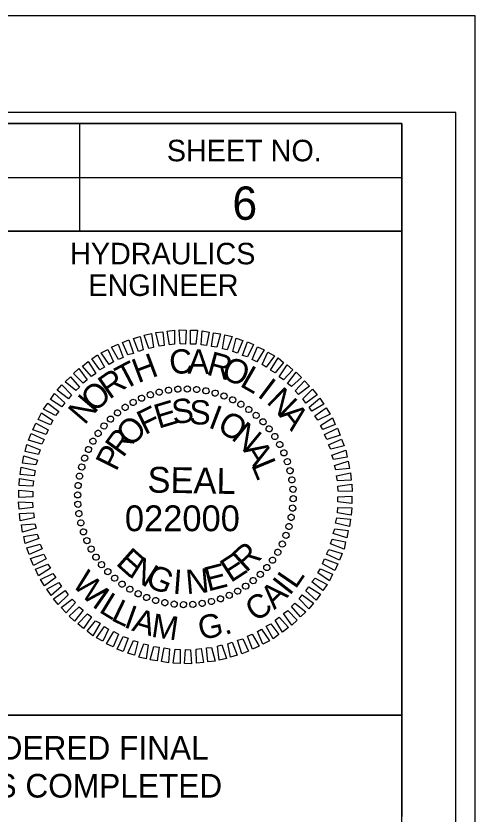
# Model space of a CAD drawing. Extents: x 1019474 to 1021158, y 503201 to 504732.
# Drawn here: x 1021051.4 to 1021158.2, y 504115.2 to 504300.7 of the extents above; entities that cross this region are included whole.
import ezdxf

# ---------------------------------------------------------------- set-up
doc = ezdxf.new("R2010")
doc.units = 0
for name, color, linetype in [('Sheet Cutting Line CELL', 7, 'Continuous'), ('Sheet Data Field CELL', 7, 'Continuous'), ('Sheet Plot Border Inside CELL', 7, 'Continuous'), ('Sheet Plot Border Outside CELL', 7, 'Continuous'), ('Sheet Professional Seal CELL', 7, 'Continuous'), ('Sheet Profile CELL', 7, 'Continuous'), ('Sheet Sticker Exception Certification CELL', 7, 'Continuous')]:
    doc.layers.add(name, color=color, linetype=linetype)

msp = doc.modelspace()

# ---------------------------------------------------------------- linework, layer by layer
at = {"layer": 'Sheet Cutting Line CELL'}
msp.add_line((1021158.22, 504300.7), (1019474.22, 504300.7), dxfattribs=at)
at = {"layer": 'Sheet Plot Border Inside CELL'}
msp.add_lwpolyline([(1019487.22, 503223.15), (1021153.72, 503223.15), (1021153.72, 504278.25), (1019487.22, 504278.25)], close=True, dxfattribs=at)
at = {"layer": 'Sheet Plot Border Outside CELL'}
msp.add_lwpolyline([(1019474.22, 503200.7), (1021158.22, 503200.7), (1021158.22, 504300.7), (1019474.22, 504300.7)], close=True, dxfattribs=at)
at = {"layer": 'Sheet Professional Seal CELL'}
for p, q in [((1021082.64, 504212.67), (1021082.64, 504212.67)), ((1021084.74, 504213.27), (1021084.74, 504213.27)), ((1021086.94, 504213.67), (1021086.94, 504213.67)), ((1021089.09, 504213.97), (1021089.09, 504213.97)), ((1021091.29, 504214.02), (1021091.29, 504214.02)), ((1021093.49, 504213.87), (1021093.49, 504213.87)), ((1021095.64, 504213.52), (1021095.64, 504213.52)), ((1021097.74, 504213.07), (1021097.74, 504213.07)), ((1021078.69, 504210.87), (1021078.69, 504210.87)), ((1021080.64, 504211.87), (1021080.64, 504211.87)), ((1021099.84, 504212.37), (1021099.84, 504212.37)), ((1021101.84, 504211.47), (1021101.84, 504211.47)), ((1021076.79, 504209.72), (1021076.79, 504209.72)), ((1021103.79, 504210.47), (1021103.79, 504210.47)), ((1021105.59, 504209.22), (1021105.59, 504209.22)), ((1021073.39, 504206.97), (1021073.39, 504206.97)), ((1021075.04, 504208.47), (1021075.04, 504208.47)), ((1021107.34, 504207.87), (1021107.34, 504207.87)), ((1021071.89, 504205.42), (1021071.89, 504205.42)), ((1021108.89, 504206.37), (1021108.89, 504206.37)), ((1021070.54, 504203.67), (1021070.54, 504203.67)), ((1021110.39, 504204.72), (1021110.39, 504204.72)), ((1021069.29, 504201.87), (1021069.29, 504201.87)), ((1021111.64, 504202.97), (1021111.64, 504202.97)), ((1021068.29, 504199.92), (1021068.29, 504199.92)), ((1021112.79, 504201.07), (1021112.79, 504201.07)), ((1021067.39, 504197.92), (1021067.39, 504197.92)), ((1021113.79, 504199.12), (1021113.79, 504199.12)), ((1021066.69, 504195.82), (1021066.69, 504195.82)), ((1021114.59, 504197.12), (1021114.59, 504197.12)), ((1021115.19, 504195.02), (1021115.19, 504195.02)), ((1021066.24, 504193.72), (1021066.24, 504193.72)), ((1021115.59, 504192.82), (1021115.59, 504192.82)), ((1021065.89, 504191.57), (1021065.89, 504191.57)), ((1021115.89, 504190.67), (1021115.89, 504190.67)), ((1021065.74, 504189.37), (1021065.74, 504189.37)), ((1021090.84, 504188.92), (1021090.84, 504188.92)), ((1021115.94, 504188.47), (1021115.94, 504188.47)), ((1021065.79, 504187.17), (1021065.79, 504187.17)), ((1021066.09, 504185.02), (1021066.09, 504185.02)), ((1021115.79, 504186.27), (1021115.79, 504186.27)), ((1021066.49, 504182.82), (1021066.49, 504182.82)), ((1021115.44, 504184.12), (1021115.44, 504184.12)), ((1021114.99, 504182.02), (1021114.99, 504182.02)), ((1021067.09, 504180.72), (1021067.09, 504180.72)), ((1021114.29, 504179.92), (1021114.29, 504179.92)), ((1021067.89, 504178.72), (1021067.89, 504178.72)), ((1021113.39, 504177.92), (1021113.39, 504177.92)), ((1021068.89, 504176.77), (1021068.89, 504176.77)), ((1021112.39, 504175.97), (1021112.39, 504175.97)), ((1021070.04, 504174.87), (1021070.04, 504174.87)), ((1021111.14, 504174.17), (1021111.14, 504174.17)), ((1021071.29, 504173.12), (1021071.29, 504173.12)), ((1021109.79, 504172.42), (1021109.79, 504172.42)), ((1021072.79, 504171.47), (1021072.79, 504171.47)), ((1021074.34, 504169.97), (1021074.34, 504169.97)), ((1021108.29, 504170.87), (1021108.29, 504170.87)), ((1021076.09, 504168.62), (1021076.09, 504168.62)), ((1021104.89, 504168.12), (1021104.89, 504168.12)), ((1021106.64, 504169.37), (1021106.64, 504169.37)), ((1021077.89, 504167.37), (1021077.89, 504167.37)), ((1021079.84, 504166.37), (1021079.84, 504166.37)), ((1021102.99, 504166.97), (1021102.99, 504166.97)), ((1021081.84, 504165.47), (1021081.84, 504165.47)), ((1021083.94, 504164.77), (1021083.94, 504164.77)), ((1021086.04, 504164.32), (1021086.04, 504164.32)), ((1021096.94, 504164.57), (1021096.94, 504164.57)), ((1021099.04, 504165.17), (1021099.04, 504165.17)), ((1021101.04, 504165.97), (1021101.04, 504165.97)), ((1021088.19, 504163.97), (1021088.19, 504163.97)), ((1021090.39, 504163.82), (1021090.39, 504163.82)), ((1021092.59, 504163.87), (1021092.59, 504163.87)), ((1021094.74, 504164.17), (1021094.74, 504164.17))]:
    msp.add_line(p, q, dxfattribs=at)
for points in [[(1021084.74, 504223.92), (1021083.94, 504227.12), (1021085.59, 504227.27), (1021085.94, 504224.07)], [(1021087.14, 504224.22), (1021086.59, 504227.42), (1021088.29, 504227.62), (1021088.34, 504224.37)], [(1021089.64, 504224.47), (1021089.39, 504227.72), (1021091.04, 504227.67), (1021090.84, 504224.42)], [(1021092.04, 504224.42), (1021092.04, 504227.67), (1021093.69, 504227.62), (1021093.24, 504224.37)], [(1021094.54, 504224.27), (1021094.74, 504227.52), (1021096.39, 504227.22), (1021095.74, 504224.07)], [(1021077.49, 504221.92), (1021076.19, 504224.82), (1021077.69, 504225.42), (1021078.74, 504222.22)], [(1021079.94, 504222.72), (1021078.79, 504225.72), (1021080.34, 504226.17), (1021080.99, 504223.07)], [(1021082.34, 504223.37), (1021081.29, 504226.52), (1021082.99, 504226.87), (1021083.39, 504223.62)], [(1021096.94, 504223.87), (1021097.39, 504227.07), (1021099.04, 504226.82), (1021098.14, 504223.72)], [(1021099.49, 504223.32), (1021099.99, 504226.57), (1021101.69, 504226.17), (1021100.54, 504223.07)], [(1021101.89, 504222.67), (1021102.64, 504225.77), (1021104.19, 504225.27), (1021102.94, 504222.32)], [(1021075.29, 504220.87), (1021073.69, 504223.67), (1021075.24, 504224.37), (1021076.39, 504221.32)], [(1021104.14, 504221.77), (1021105.29, 504224.92), (1021106.69, 504224.32), (1021105.29, 504221.42)], [(1021106.39, 504220.82), (1021107.64, 504223.77), (1021109.19, 504223.07), (1021107.49, 504220.27)], [(1021070.94, 504218.42), (1021069.09, 504220.97), (1021070.39, 504221.92), (1021072.04, 504219.02)], [(1021073.14, 504219.67), (1021071.29, 504222.37), (1021072.84, 504223.17), (1021074.09, 504220.27)], [(1021108.69, 504219.67), (1021110.04, 504222.52), (1021111.54, 504221.67), (1021109.64, 504219.07)], [(1021069.04, 504216.92), (1021066.89, 504219.32), (1021068.24, 504220.37), (1021069.99, 504217.57)], [(1021110.64, 504218.32), (1021112.39, 504221.22), (1021113.69, 504220.17), (1021111.74, 504217.72)], [(1021067.04, 504215.37), (1021064.84, 504217.57), (1021066.04, 504218.77), (1021067.99, 504216.07)], [(1021112.69, 504216.82), (1021114.54, 504219.57), (1021115.84, 504218.47), (1021113.64, 504216.12)], [(1021065.39, 504213.62), (1021062.84, 504215.67), (1021064.09, 504216.82), (1021066.19, 504214.42)], [(1021114.59, 504215.27), (1021116.64, 504217.87), (1021117.84, 504216.67), (1021115.54, 504214.52)], [(1021063.64, 504211.72), (1021061.04, 504213.67), (1021062.14, 504214.97), (1021064.34, 504212.62)], [(1021116.39, 504213.52), (1021118.54, 504215.87), (1021119.74, 504214.67), (1021117.14, 504212.72)], [(1021062.14, 504209.82), (1021059.44, 504211.52), (1021060.39, 504212.97), (1021062.79, 504210.77)], [(1021118.14, 504211.72), (1021120.44, 504213.97), (1021121.49, 504212.62), (1021118.84, 504210.72)], [(1021060.64, 504207.82), (1021057.84, 504209.32), (1021058.84, 504210.72), (1021061.44, 504208.72)], [(1021119.64, 504209.77), (1021122.09, 504211.87), (1021123.04, 504210.42), (1021120.24, 504208.82)], [(1021120.94, 504207.72), (1021123.59, 504209.62), (1021124.54, 504208.12), (1021121.64, 504206.72)], [(1021059.44, 504205.67), (1021056.59, 504206.92), (1021057.34, 504208.47), (1021060.04, 504206.62)], [(1021122.24, 504205.52), (1021125.04, 504207.27), (1021125.69, 504205.72), (1021122.84, 504204.57)], [(1021058.44, 504203.37), (1021055.34, 504204.52), (1021056.09, 504206.07), (1021058.94, 504204.47)], [(1021057.44, 504201.17), (1021054.34, 504202.07), (1021054.99, 504203.62), (1021057.99, 504202.22)], [(1021123.24, 504203.37), (1021126.19, 504204.87), (1021126.84, 504203.27), (1021123.74, 504202.27)], [(1021124.14, 504201.02), (1021127.19, 504202.32), (1021127.74, 504200.77), (1021124.64, 504199.97)], [(1021056.69, 504198.77), (1021053.59, 504199.42), (1021053.94, 504201.07), (1021057.09, 504199.82)], [(1021124.94, 504198.62), (1021128.14, 504199.77), (1021128.44, 504198.12), (1021125.29, 504197.57)], [(1021056.04, 504196.37), (1021052.94, 504196.77), (1021053.29, 504198.47), (1021056.44, 504197.42)], [(1021055.64, 504193.82), (1021052.44, 504194.12), (1021052.64, 504195.82), (1021055.89, 504195.02)], [(1021125.54, 504196.22), (1021128.69, 504197.17), (1021128.99, 504195.47), (1021125.84, 504195.17)], [(1021125.99, 504193.82), (1021129.24, 504194.52), (1021129.39, 504192.82), (1021126.19, 504192.62)], [(1021055.39, 504191.42), (1021052.14, 504191.52), (1021052.24, 504193.17), (1021055.49, 504192.62)], [(1021055.34, 504188.92), (1021052.09, 504188.77), (1021052.09, 504190.47), (1021055.34, 504190.12)], [(1021126.29, 504191.42), (1021129.54, 504191.82), (1021129.64, 504190.12), (1021126.39, 504190.22)], [(1021126.34, 504188.92), (1021129.59, 504189.07), (1021129.59, 504187.37), (1021126.34, 504187.72)], [(1021055.39, 504186.42), (1021052.14, 504186.02), (1021052.04, 504187.72), (1021055.29, 504187.62)], [(1021055.69, 504184.02), (1021052.44, 504183.32), (1021052.29, 504185.02), (1021055.49, 504185.22)], [(1021126.29, 504186.42), (1021129.54, 504186.32), (1021129.44, 504184.67), (1021126.19, 504185.22)], [(1021126.04, 504184.02), (1021129.24, 504183.72), (1021129.04, 504182.02), (1021125.79, 504182.82)], [(1021056.14, 504181.62), (1021052.99, 504180.67), (1021052.69, 504182.37), (1021055.84, 504182.67)], [(1021125.64, 504181.47), (1021128.74, 504181.07), (1021128.39, 504179.37), (1021125.24, 504180.42)], [(1021056.74, 504179.22), (1021053.54, 504178.07), (1021053.24, 504179.72), (1021056.39, 504180.27)], [(1021124.99, 504179.07), (1021128.09, 504178.42), (1021127.74, 504176.77), (1021124.59, 504178.02)], [(1021057.54, 504176.82), (1021054.49, 504175.52), (1021053.94, 504177.07), (1021057.04, 504177.87)], [(1021058.44, 504174.47), (1021055.49, 504172.97), (1021054.84, 504174.57), (1021057.94, 504175.57)], [(1021124.24, 504176.67), (1021127.34, 504175.77), (1021126.69, 504174.22), (1021123.69, 504175.62)], [(1021123.24, 504174.47), (1021126.34, 504173.32), (1021125.59, 504171.77), (1021122.74, 504173.37)], [(1021059.44, 504172.32), (1021056.64, 504170.57), (1021055.99, 504172.12), (1021058.84, 504173.27)], [(1021122.24, 504172.17), (1021125.09, 504170.92), (1021124.34, 504169.37), (1021121.64, 504171.22)], [(1021060.74, 504170.12), (1021058.09, 504168.22), (1021057.14, 504169.72), (1021060.04, 504171.12)], [(1021121.04, 504170.02), (1021123.84, 504168.52), (1021122.84, 504167.12), (1021120.24, 504169.12)], [(1021062.04, 504168.07), (1021059.59, 504165.97), (1021058.64, 504167.42), (1021061.44, 504169.02)], [(1021119.54, 504168.02), (1021122.24, 504166.32), (1021121.29, 504164.87), (1021118.89, 504167.07)], [(1021063.54, 504166.12), (1021061.24, 504163.87), (1021060.19, 504165.22), (1021062.84, 504167.12)], [(1021118.04, 504166.12), (1021120.64, 504164.17), (1021119.54, 504162.87), (1021117.34, 504165.22)], [(1021065.29, 504164.32), (1021063.14, 504161.97), (1021061.94, 504163.17), (1021064.54, 504165.12)], [(1021116.29, 504164.22), (1021118.84, 504162.17), (1021117.59, 504161.02), (1021115.49, 504163.42)], [(1021067.09, 504162.57), (1021065.04, 504159.97), (1021063.84, 504161.17), (1021066.14, 504163.32)], [(1021114.64, 504162.47), (1021116.84, 504160.27), (1021115.64, 504159.07), (1021113.69, 504161.77)], [(1021068.99, 504161.02), (1021067.14, 504158.27), (1021065.84, 504159.37), (1021068.04, 504161.72)], [(1021112.64, 504160.92), (1021114.79, 504158.52), (1021113.44, 504157.47), (1021111.69, 504160.27)], [(1021071.04, 504159.52), (1021069.29, 504156.62), (1021067.99, 504157.67), (1021069.94, 504160.12)], [(1021072.99, 504158.17), (1021071.64, 504155.32), (1021070.14, 504156.17), (1021072.04, 504158.77)], [(1021110.74, 504159.42), (1021112.59, 504156.87), (1021111.29, 504155.92), (1021109.64, 504158.82)], [(1021075.29, 504157.02), (1021074.04, 504154.07), (1021072.49, 504154.77), (1021074.19, 504157.57)], [(1021106.39, 504156.97), (1021107.99, 504154.17), (1021106.44, 504153.47), (1021105.29, 504156.52)], [(1021108.54, 504158.17), (1021110.39, 504155.47), (1021108.84, 504154.67), (1021107.59, 504157.57)], [(1021077.54, 504156.07), (1021076.39, 504152.92), (1021074.99, 504153.52), (1021076.39, 504156.42)], [(1021079.79, 504155.17), (1021079.04, 504152.07), (1021077.49, 504152.57), (1021078.74, 504155.52)], [(1021101.74, 504155.12), (1021102.89, 504152.12), (1021101.34, 504151.67), (1021100.69, 504154.77)], [(1021104.19, 504155.92), (1021105.49, 504153.02), (1021103.99, 504152.42), (1021102.94, 504155.62)], [(1021082.19, 504154.52), (1021081.69, 504151.27), (1021079.99, 504151.67), (1021081.14, 504154.77)], [(1021084.74, 504153.97), (1021084.29, 504150.77), (1021082.64, 504151.02), (1021083.54, 504154.12)], [(1021087.14, 504153.57), (1021086.94, 504150.32), (1021085.29, 504150.62), (1021085.94, 504153.77)], [(1021089.64, 504153.42), (1021089.64, 504150.17), (1021087.99, 504150.22), (1021088.44, 504153.47)], [(1021092.04, 504153.37), (1021092.29, 504150.12), (1021090.64, 504150.17), (1021090.84, 504153.42)], [(1021094.54, 504153.62), (1021095.09, 504150.42), (1021093.39, 504150.22), (1021093.34, 504153.47)], [(1021096.94, 504153.92), (1021097.74, 504150.72), (1021096.09, 504150.57), (1021095.74, 504153.77)], [(1021099.34, 504154.47), (1021100.39, 504151.32), (1021098.69, 504150.97), (1021098.29, 504154.22)]]:
    msp.add_lwpolyline(points, close=True, dxfattribs=at)
for centre, major_axis in [((1021086.92, 504213.7), (-0.113, 0.711)), ((1021089.09, 504213.94), (-0.05, 0.718)), ((1021091.28, 504214), (0.013, 0.72)), ((1021093.46, 504213.87), (0.075, 0.716)), ((1021095.63, 504213.54), (0.137, 0.707)), ((1021080.64, 504211.84), (-0.293, 0.658)), ((1021082.68, 504212.64), (-0.234, 0.681)), ((1021084.77, 504213.26), (-0.174, 0.699)), ((1021097.75, 504213.03), (0.198, 0.692)), ((1021099.83, 504212.34), (0.258, 0.672)), ((1021078.68, 504210.86), (-0.349, 0.63)), ((1021101.84, 504211.47), (0.316, 0.647)), ((1021103.76, 504210.42), (0.371, 0.617)), ((1021075.06, 504208.42), (-0.453, 0.56)), ((1021076.82, 504209.72), (-0.403, 0.597)), ((1021105.58, 504209.21), (0.423, 0.582)), ((1021073.42, 504206.97), (-0.5, 0.518)), ((1021107.3, 504207.85), (0.472, 0.543)), ((1021108.88, 504206.35), (0.518, 0.5)), ((1021071.91, 504205.38), (-0.543, 0.472)), ((1021110.33, 504204.71), (0.56, 0.453)), ((1021070.55, 504203.67), (-0.582, 0.423)), ((1021111.63, 504202.95), (0.597, 0.403)), ((1021069.34, 504201.84), (-0.617, 0.371)), ((1021112.78, 504201.08), (0.63, 0.349)), ((1021068.3, 504199.92), (-0.647, 0.316)), ((1021113.75, 504199.13), (0.658, 0.293)), ((1021067.43, 504197.91), (-0.672, 0.258)), ((1021114.56, 504197.09), (0.681, 0.234)), ((1021066.73, 504195.84), (-0.692, 0.198)), ((1021115.18, 504194.99), (0.699, 0.174)), ((1021066.22, 504193.71), (-0.707, 0.137)), ((1021065.9, 504191.55), (-0.716, 0.075)), ((1021115.61, 504192.85), (0.711, 0.113)), ((1021115.86, 504190.67), (0.718, 0.05)), ((1021065.77, 504189.36), (-0.72, 0.013)), ((1021115.92, 504188.49), (0.72, -0.013)), ((1021065.82, 504187.18), (-0.718, -0.05)), ((1021115.78, 504186.3), (0.716, -0.075)), ((1021066.07, 504185), (-0.711, -0.113)), ((1021115.46, 504184.14), (0.707, -0.137)), ((1021066.51, 504182.86), (-0.699, -0.174)), ((1021114.95, 504182.01), (0.692, -0.198)), ((1021067.13, 504180.76), (-0.681, -0.234)), ((1021067.93, 504178.72), (-0.658, -0.293)), ((1021114.26, 504179.94), (0.672, -0.258)), ((1021068.91, 504176.77), (-0.63, -0.349)), ((1021113.38, 504177.93), (0.647, -0.316)), ((1021070.05, 504174.9), (-0.597, -0.403)), ((1021112.34, 504176.01), (0.617, -0.371)), ((1021071.35, 504173.14), (-0.56, -0.453)), ((1021111.13, 504174.18), (0.582, -0.423)), ((1021072.8, 504171.5), (-0.518, -0.5)), ((1021108.26, 504170.88), (0.5, -0.518)), ((1021109.77, 504172.47), (0.543, -0.472)), ((1021074.39, 504170), (-0.472, -0.543)), ((1021106.63, 504169.43), (0.453, -0.56)), ((1021076.1, 504168.63), (-0.423, -0.582)), ((1021077.92, 504167.43), (-0.371, -0.617)), ((1021104.87, 504168.13), (0.403, -0.597)), ((1021079.85, 504166.38), (-0.316, -0.647)), ((1021081.85, 504165.51), (-0.258, -0.672)), ((1021101.04, 504166.01), (0.293, -0.658)), ((1021103, 504166.99), (0.349, -0.63)), ((1021083.93, 504164.82), (-0.198, -0.692)), ((1021086.06, 504164.31), (-0.137, -0.707)), ((1021088.22, 504163.98), (-0.075, -0.716)), ((1021090.4, 504163.85), (-0.013, -0.72)), ((1021092.59, 504163.91), (0.05, -0.718)), ((1021094.77, 504164.15), (0.113, -0.711)), ((1021096.91, 504164.59), (0.174, -0.699)), ((1021099.01, 504165.21), (0.234, -0.681))]:
    msp.add_ellipse(centre, major_axis=major_axis, ratio=0.999708, dxfattribs=at)
at = {"layer": 'Sheet Profile CELL'}
for p, q in [((1021066.22, 504275.65), (1021066.22, 504250.65)), ((1020941.17, 504263.15), (1021141.22, 504263.15))]:
    msp.add_line(p, q, dxfattribs=at)
for points in [[(1021141.22, 504275.7), (1019641.22, 504275.7), (1019641.22, 503225.7), (1021141.22, 503225.7)], [(1020941.17, 504275.7), (1021141.22, 504275.7), (1021141.22, 504250.65), (1020941.17, 504250.65)], [(1021041.22, 504250.65), (1021141.22, 504250.65), (1021141.22, 504138.15), (1021041.22, 504138.15)]]:
    msp.add_lwpolyline(points, close=True, dxfattribs=at)
at = {"layer": 'Sheet Sticker Exception Certification CELL'}
for p, q in [((1020941.17, 504138.15), (1021141.21, 504138.15)), ((1020941.17, 504138.15), (1021141.21, 504138.15)), ((1021141.21, 504138.13), (1021141.21, 504114.63)), ((1021141.21, 504138.13), (1021141.21, 504114.63))]:
    msp.add_line(p, q, dxfattribs=at)

# ---------------------------------------------------------------- texts
at = {"layer": 'Sheet Data Field CELL'}
msp.add_text('6', height=7.75, dxfattribs=at).set_placement((1021101.78, 504253.31))
at = {"layer": 'Sheet Professional Seal CELL'}
for s, height, rotation, p in [('H', 5.64, 20.6195, (1021079.79, 504215.27)), ('C', 5.64, 6.2199, (1021087.39, 504217.27)), ('A', 5.64, 359.0203, (1021091.34, 504217.57)), ('R', 5.64, 344.6211, (1021095.54, 504217.37)), ('T', 5.64, 27.8198, (1021076.54, 504213.62)), ('O', 5.64, 337.4212, (1021098.89, 504216.62)), ('R', 5.64, 35.0205, (1021073.14, 504211.42)), ('L', 5.64, 330.2209, (1021103.29, 504214.77)), ('I', 5.64, 323.0201, (1021107.34, 504212.37)), ('O', 5.64, 42.2217, (1021069.69, 504208.32)), ('N', 5.64, 315.8189, (1021109.49, 504210.82)), ('N', 5.64, 49.4235, (1021067.39, 504205.42)), ('E', 5.64, 16.6111, (1021084.59, 504204.72)), ('S', 5.64, 7.2556, (1021088.04, 504205.77)), ('S', 5.64, 357.9004, (1021091.64, 504205.82)), ('F', 5.64, 25.967, (1021081.39, 504203.22)), ('I', 5.64, 339.1896, (1021095.94, 504205.12)), ('A', 5.64, 308.6172, (1021112.44, 504207.87)), ('O', 5.64, 44.6812, (1021078.09, 504200.27)), ('O', 5.64, 329.8335, (1021097.94, 504204.42)), ('N', 5.64, 320.4766, (1021101.29, 504202.42)), ('R', 5.64, 54.0397, (1021076.34, 504197.82)), ('P', 5.64, 63.3989, (1021074.74, 504194.62)), ('A', 5.64, 301.7603, (1021104.14, 504199.82)), ('L', 5.64, 292.4008, (1021106.09, 504196.37)), ('SEAL', 5.998, 359, (1021081.99, 504189.92)), ('022000', 5.998, 360, (1021076.76, 504180.92)), ('R', 5.64, 42.4814, (1021104.94, 504171.17)), ('E', 5.64, 318.2769, (1021074.44, 504173.27)), ('E', 5.64, 33.1241, (1021101.39, 504168.82)), ('N', 5.64, 327.634, (1021077.44, 504170.57)), ('E', 5.64, 14.4118, (1021096.09, 504166.87)), ('W', 5.5, 313.3349, (1021064.26, 504168.49)), ('G', 5.64, 336.9902, (1021081.24, 504168.32)), ('I', 5.64, 355.7012, (1021087.79, 504166.42)), ('N', 5.64, 5.0564, (1021091.14, 504166.27)), ('I', 5.5, 52.0797, (1021115.08, 504165.75)), ('L', 5.5, 55.6002, (1021116.46, 504167.29)), ('A', 5.5, 43.8939, (1021111.54, 504162.54)), ('I', 5.5, 324.941, (1021068.91, 504163.56)), ('L', 5.5, 328.4615, (1021070.51, 504162.26)), ('C', 5.5, 35.0212, (1021107.22, 504159.66)), ('L', 5.5, 334.2717, (1021073.31, 504160.34)), ('I', 5.5, 340.0819, (1021076.3, 504158.71)), ('A', 5.5, 343.6024, (1021078.18, 504157.87)), ('M', 5.5, 351.7882, (1021082.73, 504156.39)), ('G', 5.5, 11.9092, (1021094.42, 504155.58)), ('.', 5.5, 21.8409, (1021100.12, 504156.7))]:
    msp.add_text(s, height=height, rotation=rotation, dxfattribs=at).set_placement(p)
at = {"layer": 'Sheet Profile CELL'}
for s, p in [('SHEET NO.', (1021086.53, 504266.91)), ('HYDRAULICS', (1021064.03, 504242.96)), ('ENGINEER', (1021068.28, 504235.61))]:
    msp.add_text(s, height=5, dxfattribs=at).set_placement(p)
at = {"layer": 'Sheet Sticker Exception Certification CELL'}
for s, p in [('DOCUMENT NOT CONSIDERED FINAL', (1020962.24, 504127.8)), ('DOCUMENT NOT CONSIDERED FINAL', (1020962.24, 504127.8)), ('UNLESS ALL SIGNATURES COMPLETED', (1020957.17, 504119)), ('UNLESS ALL SIGNATURES COMPLETED', (1020957.17, 504119))]:
    msp.add_text(s, height=5.5, dxfattribs=at).set_placement(p)

doc.saveas('drawing.dxf')
